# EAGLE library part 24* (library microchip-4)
Serial EEPROM I2C
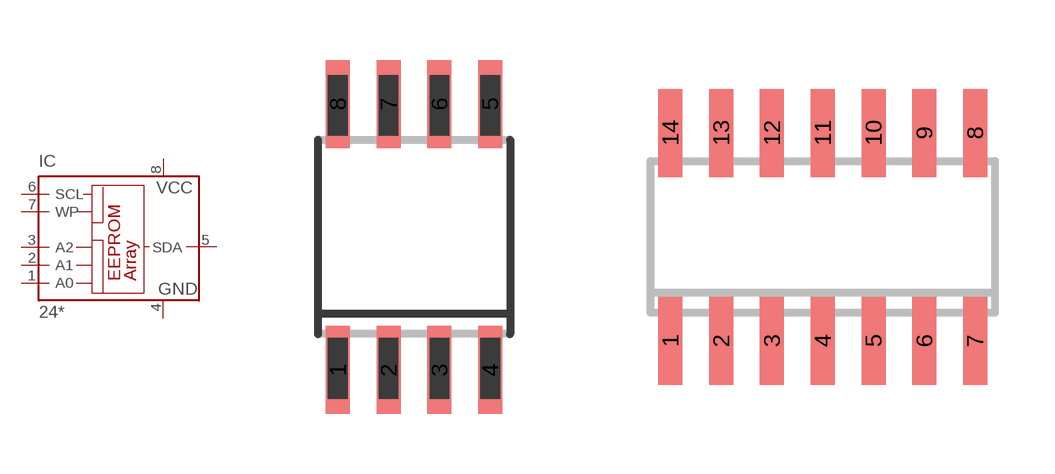
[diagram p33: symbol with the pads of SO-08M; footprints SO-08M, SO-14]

Designator prefix IC

## 24AA01SM, 24AA02SM, 24AA04SM, 24AA08SM, 24AA128SM, 24AA16SM, 24AA32ASM, 24C01ASM, 24C02ASM, 24C04ASM, 24C08BSM, 24C32ASM, 24C64SM, 24CL04BSM, 24LC08BSM, 24LC128SM, 24LC16BSM, 24LC32ASM, 24LC64SM  [SO-08M]
1  A0  in
2  A1  in
3  A2  in
4  GND  pwr
5  SDA
6  SCL  in
7  WP  in
8  VCC  pwr

## 24AA04SL, 24AA08SL, 24AA16SL, 24C01ASL, 24C02ASL, 24C04ASL, 24C08BSL, 24C16BSL, 24CL04ASL, 24LC08BSL, 24LC16BSL  [SO-14]
2  A0  in
3  A1  in
5  A2  in
6  GND  pwr
9  SDA
10  SCL  in
12  WP  in
13  VCC  pwr

## 24AA01P, 24AA02P, 24AA04P, 24AA08P, 24AA128P, 24AA16P, 24AA256P, 24AA32AP, 24AA64P, 24C01AP, 24C02AP, 24C04AP, 24C08BP, 24C16BP, 24C32AP, 24C64P, 24CL04BP, 24LC01P, 24LC024P, 24LC025P, 24LC04P, 24LC08BP, 24LC128P, 24LC16BP, 24LC256P, 24LC32AP, 24LC64P, 24LCS52P  [DIL8]
Pads as for SO-08M

## 24AA01SN, 24AA02SN, 24AA04SN, 24AA08SN, 24AA128SN, 24AA16SN, 24AA256SN, 24AA32ASN, 24AA64SN, 24C08BSN, 24C16BSN, 24C32ASN, 24CL04BSN, 24LC024SN, 24LC025SN, 24LC08BSN, 24LC128SN, 24LC16BSN, 24LC256SN, 24LC32ASN, 24LC64SN, 24LCS52SN  [SO-08]
Pads as for SO-08M

## 24AA128ST, 24AA64ST, 24C64ST, 24LC024ST, 24LC025ST, 24LC128ST, 24LC64ST, 24LCS52ST  [TSSOP8]
Pads as for SO-08M

## Footprint SO-08M (pad centres in mm)
Small Outline Medium Plastic Gull Wing 207-mil body, package type SM
smd 0.6 x 2.2: 1 -1.905,-3.33; 2 -0.635,-3.33; 3 0.635,-3.33; 4 1.905,-3.33; 5 1.905,3.33; 6 0.635,3.33; 7 -0.635,3.33; 8 -1.905,3.33

## Footprint SO-14 (pad centres in mm)
Small Outline Narrow Plastic Gull Wing 150-mil body, package type SL
smd 0.6 x 2.2: 1 -3.81,-2.6; 2 -2.54,-2.6; 3 -1.27,-2.6; 4 0,-2.6; 5 1.27,-2.6; 6 2.54,-2.6; 7 3.81,-2.6; 8 3.81,2.6; 9 2.54,2.6; 10 1.27,2.6; 11 0,2.6; 12 -1.27,2.6; 13 -2.54,2.6; 14 -3.81,2.6

## Footprint DIL8 (pad centres in mm)
Dual In Line package type P
drill 0.813 long: 1 -3.81,-3.81; 2 -1.27,-3.81; 3 1.27,-3.81; 4 3.81,-3.81; 5 3.81,3.81; 6 1.27,3.81; 7 -1.27,3.81; 8 -3.81,3.81

## Footprint SO-08 (pad centres in mm)
Small Outline Narrow Plastic Gull Wing 150-mil body, package type SN
smd 0.6 x 2.2: 1 -1.905,-2.6; 2 -0.635,-2.6; 3 0.635,-2.6; 4 1.905,-2.6; 5 1.905,2.6; 6 0.635,2.6; 7 -0.635,2.6; 8 -1.905,2.6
